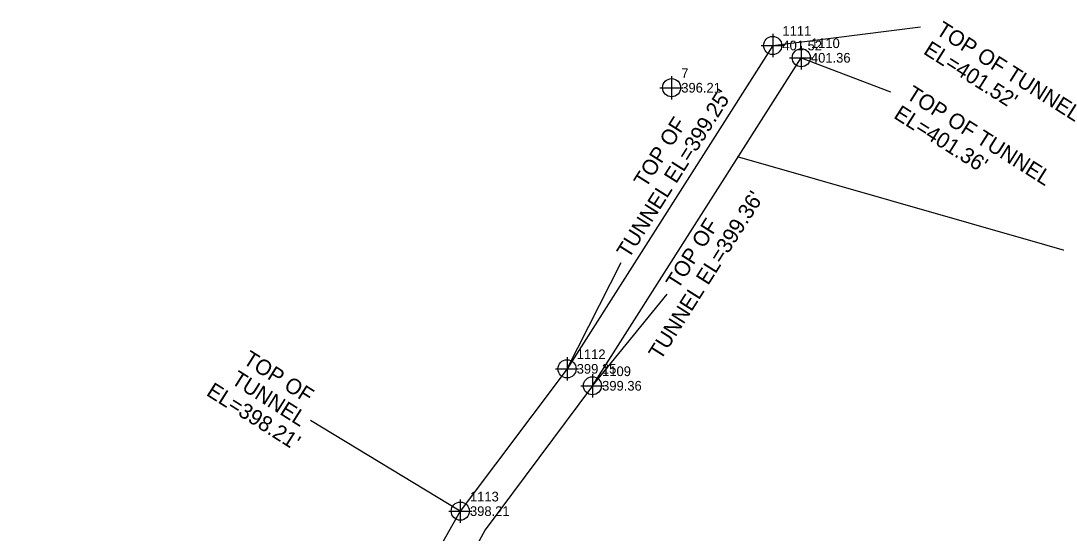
# Model space of a CAD drawing. Extents: x 2024146 to 2025516, y 819906 to 820765.
# Drawn here: x 2024651.6 to 2024918.9, y 820520.8 to 820653.1 of the extents above; entities that cross this region are included whole.
import ezdxf

# ---------------------------------------------------------------- set-up
doc = ezdxf.new("R2010")
doc.units = 0
for name, color, linetype in [('Sheet Block Revision CELL', 7, 'Continuous'), ('Sheet Layout Plan Border', 7, 'Continuous'), ('Sheet Layout Profile Border Port 2', 7, 'Continuous'), ('Sheet Plot Border Inside CELL', 7, 'Continuous'), ('Sheet Plot Border Outside CELL', 7, 'Continuous'), ('Sheet Sticker Incomplete CELL', 7, 'Continuous')]:
    doc.layers.add(name, color=color, linetype=linetype)

msp = doc.modelspace()

# ---------------------------------------------------------------- linework, layer by layer
at = {"layer": 'Sheet Layout Plan Border'}
for points in [[(2024845.72, 820649.74), (2024845.72, 820646.74)], [(2024842.72, 820646.74), (2024845.72, 820646.74)], [(2024845.72, 820646.74), (2024848.72, 820646.74)], [(2024845.72, 820646.74), (2024845.72, 820643.74)], [(2024853.09, 820646.57), (2024853.09, 820643.57)], [(2024850.09, 820643.57), (2024853.09, 820643.57)], [(2024853.09, 820643.57), (2024856.09, 820643.57)], [(2024853.09, 820643.57), (2024853.09, 820640.57)], [(2024819.62, 820638.84), (2024819.62, 820635.84)], [(2024816.62, 820635.84), (2024819.62, 820635.84)], [(2024819.62, 820635.84), (2024822.62, 820635.84)], [(2024819.62, 820635.84), (2024819.62, 820632.84)], [(2024792.63, 820566.28), (2024792.63, 820563.28)], [(2024789.63, 820563.28), (2024792.63, 820563.28)], [(2024792.63, 820563.28), (2024795.63, 820563.28)], [(2024792.63, 820563.28), (2024792.63, 820560.28)], [(2024799.19, 820561.91), (2024799.19, 820558.91)], [(2024796.19, 820558.91), (2024799.19, 820558.91)], [(2024799.19, 820558.91), (2024802.19, 820558.91)], [(2024799.19, 820558.91), (2024799.19, 820555.91)], [(2024765.08, 820529.55), (2024765.08, 820526.55)], [(2024762.08, 820526.55), (2024765.08, 820526.55)], [(2024765.08, 820526.55), (2024768.08, 820526.55)], [(2024765.08, 820526.55), (2024765.08, 820523.55)]]:
    msp.add_lwpolyline(points, dxfattribs=at)
for centre in [(2024845.72, 820646.74), (2024853.09, 820643.57), (2024819.62, 820635.84), (2024792.63, 820563.28), (2024799.19, 820558.91), (2024765.08, 820526.55)]:
    msp.add_circle(centre, 2.34, dxfattribs=at)
at = {"layer": 'Sheet Plot Border Inside CELL'}
for points in [[(2024845.72, 820646.74), (2024883.88, 820651.53)], [(2024853.09, 820643.57), (2024876.14, 820634.77)], [(2024836.51, 820618.08), (2024936.03, 820589.62)], [(2024792.63, 820563.28), (2024806.57, 820590.74)], [(2024799.19, 820558.91), (2024818.45, 820582.52)], [(2024765.08, 820526.55), (2024726.45, 820549.91)]]:
    msp.add_lwpolyline(points, dxfattribs=at)
at = {"layer": 'Sheet Sticker Incomplete CELL'}
for points in [[(2024845.72, 820646.74), (2024792.63, 820563.28), (2024765.08, 820526.55)], [(2024799.19, 820558.91), (2024853.09, 820643.57)], [(2024799.19, 820558.91), (2024771.48, 820521.75), (2024748.78, 820479.97)], [(2024765.08, 820526.55), (2024737.81, 820478.22), (2024651.62, 820339.93)]]:
    msp.add_lwpolyline(points, dxfattribs=at)

# ---------------------------------------------------------------- texts
at = {"layer": 'Sheet Block Revision CELL'}
for s, p in [('1111', (2024848.22, 820649.24)), ('1110', (2024855.59, 820646.07)), ('7', (2024822.12, 820638.34)), ('1112', (2024795.13, 820565.78)), ('1109', (2024801.69, 820561.41)), ('1113', (2024767.58, 820529.05))]:
    msp.add_text(s, height=2.5, dxfattribs=at).set_placement(p)
at = {"layer": 'Sheet Layout Profile Border Port 2'}
for s, p in [('401.52', (2024848.22, 820645.49)), ('401.36', (2024855.59, 820642.32)), ('396.21', (2024822.12, 820634.59)), ('399.25', (2024795.13, 820562.03)), ('399.36', (2024801.69, 820557.66)), ('398.21', (2024767.58, 820525.3))]:
    msp.add_text(s, height=2.5, dxfattribs=at).set_placement(p)
at = {"layer": 'Sheet Plot Border Outside CELL'}
for s, rotation, p in [('TOP OF TUNNEL', 327.6834, (2024887.58, 820649.82)), ("EL=401.52'", 327.6834, (2024884.37, 820644.75)), ('TOP OF TUNNEL', 327.6834, (2024879.9, 820633.24)), ("TUNNEL EL=399.25'", 57.7354, (2024808.57, 820591.53)), ("EL=401.36'", 327.6834, (2024876.69, 820628.17)), ('TOP OF ', 57.7354, (2024812.98, 820609.76)), ("TUNNEL EL=399.36'", 57.6554, (2024816.79, 820565.31)), ('TOP OF ', 57.6554, (2024821.27, 820583.61)), ('TOP OF', 327.6834, (2024708.73, 820564.83)), ('TUNNEL', 327.6834, (2024705.68, 820559.66)), ("EL=398.21'", 327.6834, (2024699.28, 820556.6))]:
    msp.add_text(s, height=4, rotation=rotation, dxfattribs=at).set_placement(p)

doc.saveas('drawing.dxf')
